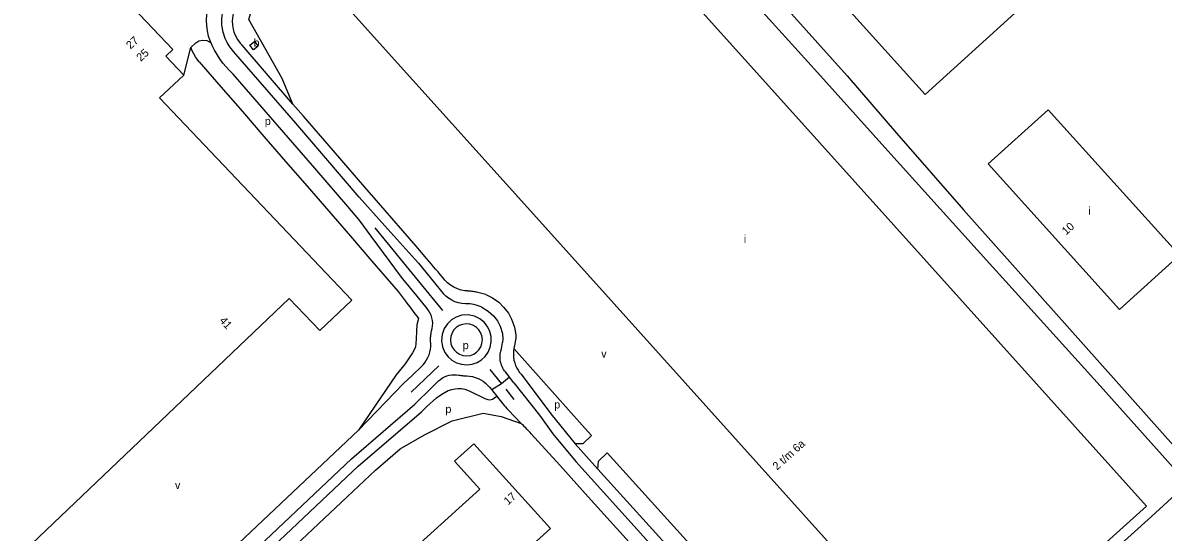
# Model space of a CAD drawing. Extents: x 156097 to 158136, y 385644 to 388348.
# Drawn here: x 156386 to 156956, y 387555 to 387809 of the extents above; entities that cross this region are included whole.
import ezdxf

# ---------------------------------------------------------------- set-up
doc = ezdxf.new("R2010")
doc.units = 0
for name, color, linetype in [('BLT_Basislijn', 7, 'Continuous'), ('BLT_Bebouwing', 7, 'Continuous'), ('BLT_Centroide', 7, 'Continuous'), ('BLT_Huisnummer', 7, 'Continuous'), ('BLT_Huisnummer_reeks', 7, 'Continuous'), ('BLT_Vlakafsluiter', 7, 'Continuous')]:
    doc.layers.add(name, color=color, linetype=linetype)

msp = doc.modelspace()

# ---------------------------------------------------------------- linework, layer by layer
at = {"layer": 'BLT_Basislijn'}
for p, q in [((156797.75, 387782.82), (156644.38, 387953.86)), ((156782.89, 387784.42), (156650.83, 387931.69)), ((156466.18, 387783.18), (156469.74, 387796.91)), ((156782.89, 387784.42), (156818.11, 387745.39)), ((156838.17, 387723.2), (156818.11, 387745.39)), ((156561.75, 387706.8), (156583.3, 387680.38)), ((156583.45, 387689.27), (156595.92, 387674.06)), ((156869.02, 387689.03), (156874, 387683.54)), ((156583.3, 387680.38), (156595.45, 387665.58)), ((156615.21, 387667.23), (156614.27, 387667.61)), ((156583.52, 387661.55), (156582.76, 387658.42)), ((156582.57, 387655.34), (156582.33, 387651.33)), ((156582.76, 387658.42), (156582.57, 387655.34)), ((156589.89, 387654.57), (156590.07, 387655.37)), ((156582.33, 387651.33), (156582.09, 387647.33)), ((156589.62, 387648.96), (156589.52, 387650.42)), ((156580.51, 387644.53), (156576.87, 387638.94)), ((156582.09, 387647.33), (156580.51, 387644.53)), ((156576.87, 387638.94), (156572.33, 387633.42)), ((156593.68, 387637.95), (156579.9, 387624.84)), ((156572.33, 387633.42), (156553.53, 387605.91)), ((156619.24, 387636.12), (156624.93, 387628.99)), ((156631.22, 387629.55), (156629.05, 387632.32)), ((156553.53, 387605.91), (156576.01, 387629.14)), ((156627.09, 387626.3), (156631.09, 387621.18)), ((156631.22, 387629.55), (156643.96, 387613.36)), ((156643.96, 387613.36), (156650.67, 387604.05)), ((156650.67, 387604.05), (156662.1, 387590.2)), ((156665.62, 387598.94), (156661.89, 387598.94)), ((156661.89, 387598.94), (156673.23, 387586.41)), ((156665.62, 387598.94), (156670.05, 387603.2)), ((156787.54, 387473.33), (156677.9, 387594.53)), ((156453.11, 387500.09), (156549.98, 387591.56)), ((156456.58, 387496.48), (156553.32, 387587.84)), ((156673.23, 387586.41), (156780.91, 387467.5))]:
    msp.add_line(p, q, dxfattribs=at)
for points in [[(156583.45, 387689.27), (156578.73, 387694.48), (156566.66, 387707.87), (156553.82, 387722.16), (156537.27, 387741.73), (156522.14, 387759.18), (156491.06, 387794.97), (156489.86, 387796.38), (156488.92, 387797.7), (156487.91, 387799.38), (156486.9, 387801.42), (156485.84, 387804.66), (156485.26, 387808.12), (156485.21, 387811.17), (156485.77, 387815.29), (156486.44, 387817.6), (156487.19, 387819.37), (156488.39, 387821.56), (156489.76, 387823.53), (156492.22, 387826.16), (156602.46, 387928.57), (156606.37, 387932.32), (156616.1, 387941.58), (156622.93, 387948.05)], [(156629.52, 387949.24), (156618.62, 387938.99), (156570.53, 387893.25), (156498.62, 387825.16), (156496.11, 387823.09), (156494.55, 387821.31), (156493.23, 387819.46), (156492.38, 387817.85), (156491.57, 387815.96), (156490.9, 387813.77), (156490.56, 387811.73), (156490.41, 387809.85), (156490.47, 387808.46), (156490.75, 387806.78), (156491.23, 387804.79), (156491.95, 387803.03), (156493.06, 387800.95), (156494.35, 387799.07), (156495.29, 387798.03)], [(156520.76, 387768.68), (156515.32, 387781.45), (156498.76, 387810.93), (156500.45, 387816.59), (156620.2, 387930.86), (156627.77, 387938.06), (156650.83, 387931.69)], [(156478.58, 387802.58), (156477.98, 387805.26), (156477.64, 387807.83), (156477.57, 387810.54), (156477.71, 387813.25), (156478.08, 387816.16)], [(156469.74, 387796.91), (156472.22, 387799.22), (156473.78, 387800.26), (156475.52, 387800.59), (156477.63, 387800.48), (156479.8, 387799.34)], [(156479.8, 387799.34), (156479.43, 387800.21), (156478.58, 387802.58)], [(156490.91, 387783.63), (156489.09, 387785.37), (156487.36, 387787.22), (156485.73, 387789.18), (156484.22, 387791.24), (156482.82, 387793.38), (156481.56, 387795.6), (156480.43, 387797.88), (156479.8, 387799.34)], [(156520.76, 387768.68), (156495.29, 387798.03)], [(156473.26, 387790.65), (156472.02, 387792.32), (156470.42, 387795.19), (156469.74, 387796.91)], [(156473.9, 387789.78), (156473.26, 387790.65)], [(156473.9, 387789.78), (156484.69, 387777.34), (156495.48, 387764.91), (156506.28, 387752.47), (156517.07, 387740.04), (156527.86, 387727.61), (156538.65, 387715.17), (156549.45, 387702.74), (156560.24, 387690.31), (156573.4, 387675.14)], [(156574.52, 387682.96), (156559.8, 387702.79), (156554.31, 387710.2), (156553.69, 387710.97), (156548.27, 387717.51), (156531.73, 387736.66), (156516.25, 387754.49), (156490.91, 387783.63)], [(156797.75, 387782.82), (156822.39, 387754.16)], [(156587.71, 387691.35), (156582.39, 387697.7), (156563.47, 387719.41), (156556.63, 387727.22), (156540.95, 387745.35), (156525.98, 387762.66), (156520.76, 387768.68)], [(156822.39, 387754.16), (156856.01, 387715.91), (156962.28, 387596.74)], [(156869.02, 387689.03), (156838.17, 387723.2)], [(156595.53, 387682.2), (156594.41, 387683.51), (156593.29, 387684.82), (156592.18, 387686.12), (156591.06, 387687.43), (156589.95, 387688.74), (156588.83, 387690.04), (156587.71, 387691.35)], [(156874, 387683.54), (156924.28, 387627.93)], [(156587.8, 387666.65), (156582.86, 387672.68), (156575.74, 387681.37), (156574.52, 387682.96)], [(156606.62, 387675.42), (156604.78, 387675.79), (156602.97, 387676.38), (156601.22, 387677.18), (156599.56, 387678.19), (156598.05, 387679.38), (156596.69, 387680.73), (156595.53, 387682.2)], [(156573.4, 387675.14), (156577.36, 387669.83), (156578.24, 387668.65), (156579.12, 387667.46), (156580, 387666.28), (156580.88, 387665.1), (156581.76, 387663.92), (156582.64, 387662.73), (156583.52, 387661.55)], [(156607, 387668.94), (156605.24, 387669.07), (156603.48, 387669.41), (156601.75, 387669.97), (156600.1, 387670.73), (156598.56, 387671.69), (156597.16, 387672.81), (156595.92, 387674.06)], [(156608.5, 387675.29), (156608.23, 387675.31), (156607.96, 387675.33), (156607.7, 387675.35), (156607.43, 387675.36), (156607.16, 387675.38), (156606.89, 387675.4), (156606.62, 387675.42)], [(156612.53, 387674.78), (156611.96, 387674.89), (156611.39, 387674.99), (156610.81, 387675.08), (156610.24, 387675.15), (156609.66, 387675.21), (156609.08, 387675.26), (156608.5, 387675.29)], [(156617.12, 387673.59), (156616.46, 387673.76), (156615.81, 387673.93), (156615.15, 387674.1), (156614.5, 387674.27), (156613.84, 387674.44), (156613.19, 387674.61), (156612.53, 387674.78)], [(156617.12, 387673.59), (156620.47, 387671.91), (156623.61, 387669.76), (156626.21, 387667.16), (156628.44, 387664.29), (156629.99, 387661.25), (156631.45, 387657.26), (156632.12, 387653.44), (156632.2, 387651.75), (156631.57, 387648.1)], [(156590.07, 387655.37), (156590.38, 387656.63), (156590.57, 387657.94), (156590.6, 387659.28), (156590.49, 387660.63), (156590.22, 387661.96), (156589.8, 387663.26), (156589.25, 387664.48), (156588.58, 387665.62), (156587.8, 387666.65)], [(156614.27, 387667.61), (156613.28, 387667.97), (156612.26, 387668.27), (156611.22, 387668.52), (156610.17, 387668.71), (156609.12, 387668.84), (156608.06, 387668.92), (156607, 387668.94)], [(156615.21, 387667.23), (156618.4, 387665.19), (156621, 387662.86), (156622.96, 387660.42), (156624.31, 387657.72), (156625.43, 387654.14), (156625.66, 387651.32), (156625.53, 387649.54)], [(156618.21, 387657.35), (156616.54, 387659.55), (156614.24, 387661.44), (156611.43, 387662.78), (156608.33, 387663.38), (156605.22, 387663.2), (156602.38, 387662.31), (156600, 387660.91), (156597.98, 387659.01), (156596.34, 387656.53), (156595.3, 387653.6), (156595.02, 387650.45), (156595.52, 387647.38), (156596.7, 387644.65), (156598.34, 387642.42)], [(156589.52, 387650.42), (156589.51, 387650.88), (156589.51, 387651.35), (156589.53, 387651.81), (156589.56, 387652.28), (156589.6, 387652.74), (156589.65, 387653.2), (156589.72, 387653.66), (156589.8, 387654.12), (156589.89, 387654.57)], [(156598.34, 387642.42), (156600.19, 387640.8), (156602.46, 387639.51), (156605.03, 387638.71), (156607.74, 387638.47), (156610.41, 387638.82), (156612.86, 387639.69), (156614.97, 387640.97), (156616.78, 387642.64), (156618.31, 387644.75), (156619.39, 387647.22), (156619.92, 387649.89), (156619.86, 387652.58), (156619.25, 387655.11), (156618.21, 387657.35)], [(156602.4, 387657.12), (156601.22, 387655.93), (156600.27, 387654.42), (156599.66, 387652.67), (156599.47, 387650.79), (156599.72, 387648.95), (156600.35, 387647.29), (156601.27, 387645.89), (156602.46, 387644.71), (156603.96, 387643.75), (156605.71, 387643.14), (156607.59, 387642.94), (156609.43, 387643.19), (156611.1, 387643.82), (156612.5, 387644.73)], [(156612.5, 387644.73), (156613.68, 387645.92), (156614.63, 387647.43), (156615.24, 387649.18), (156615.43, 387651.05), (156615.19, 387652.9), (156614.55, 387654.57), (156613.64, 387655.97), (156612.45, 387657.15), (156610.94, 387658.1), (156609.19, 387658.72), (156607.31, 387658.91), (156605.47, 387658.66), (156603.8, 387658.03), (156602.4, 387657.12)], [(156585.02, 387637.64), (156585.97, 387638.63), (156586.83, 387639.72), (156587.59, 387640.9), (156588.25, 387642.16), (156588.78, 387643.47), (156589.19, 387644.83), (156589.46, 387646.21), (156589.6, 387647.59), (156589.62, 387648.96)], [(156625.36, 387648.68), (156625.53, 387649.54)], [(156626.95, 387634.94), (156626.49, 387635.54), (156626.06, 387636.19), (156625.67, 387636.87), (156625.32, 387637.58), (156625.02, 387638.31), (156624.76, 387639.07), (156624.56, 387639.85), (156624.42, 387640.64), (156624.32, 387641.43), (156624.28, 387642.22), (156624.3, 387643.01), (156624.36, 387643.79), (156624.48, 387644.56), (156624.64, 387645.31)], [(156624.64, 387645.31), (156624.93, 387646.42), (156625.17, 387647.55), (156625.36, 387648.68)], [(156631.22, 387646.66), (156631.01, 387645.19), (156630.94, 387643.71), (156631.02, 387642.24), (156631.24, 387640.8), (156631.6, 387639.42), (156632.07, 387638.11), (156632.65, 387636.87), (156633.32, 387635.73), (156634.06, 387634.68), (156634.85, 387633.74)], [(156631.57, 387648.1), (156631.22, 387646.66)], [(156670.05, 387603.2), (156665.35, 387608.41), (156631.22, 387646.66)], [(156576.01, 387629.14), (156580.48, 387633.36), (156585.02, 387637.64)], [(156593.51, 387630.45), (156594.43, 387631.21), (156595.44, 387631.89), (156596.53, 387632.46), (156597.69, 387632.92), (156598.89, 387633.26), (156600.12, 387633.46), (156601.35, 387633.54), (156602.57, 387633.48), (156603.75, 387633.31)], [(156603.75, 387633.31), (156604.18, 387633.23), (156604.62, 387633.17), (156605.05, 387633.11), (156605.49, 387633.05), (156605.93, 387633.01), (156606.36, 387632.97), (156606.8, 387632.95), (156607.24, 387632.93), (156607.68, 387632.91)], [(156607.68, 387632.91), (156609.09, 387632.81), (156610.51, 387632.57), (156611.92, 387632.19), (156613.29, 387631.67), (156614.6, 387631.01), (156615.85, 387630.23), (156617, 387629.34), (156618.05, 387628.36), (156618.98, 387627.3)], [(156629.05, 387632.32), (156628.67, 387632.79), (156626.95, 387634.94)], [(156634.85, 387633.74), (156649.59, 387613.99), (156661.89, 387598.94)], [(156553.32, 387587.84), (156585.02, 387615.04), (156587.73, 387617.66), (156592.43, 387621.9), (156595.23, 387623.89), (156598.31, 387625.6), (156600.12, 387626.21), (156601.82, 387626.53), (156603.35, 387626.6), (156605.08, 387626.57), (156606.64, 387626.24), (156608.76, 387625.43), (156616.75, 387621.64), (156618.09, 387621.09), (156619.16, 387621.06), (156620.47, 387621.32), (156622.68, 387622.73)], [(156584.26, 387621.26), (156587.65, 387624.63), (156593.51, 387630.45)], [(156618.98, 387627.3), (156620.09, 387625.96)], [(156924.28, 387627.93), (156967.86, 387579.23)], [(156549.98, 387591.56), (156581.65, 387618.74), (156584.26, 387621.26)], [(156620.09, 387625.96), (156620.47, 387625.5), (156622.68, 387622.73)], [(156622.68, 387622.73), (156623.04, 387622.29), (156626.35, 387618.2), (156626.99, 387617.42), (156627.6, 387616.65), (156628.28, 387615.93), (156634.84, 387609.22)], [(156561.98, 387585.89), (156574.33, 387596.58), (156586.47, 387603.58), (156600.32, 387610.43), (156615.88, 387614.29), (156624.87, 387612.72), (156634.84, 387609.22)], [(156639.85, 387604.07), (156639.31, 387604.66), (156638.77, 387605.24), (156638.22, 387605.83), (156637.67, 387606.4), (156637.11, 387606.98), (156636.55, 387607.54), (156635.98, 387608.11), (156635.41, 387608.67), (156634.84, 387609.22)], [(156457.96, 387515.67), (156553.53, 387605.91)], [(156639.85, 387604.07), (156654.08, 387588.33), (156668.32, 387572.59), (156682.55, 387556.85), (156696.79, 387541.11), (156711.03, 387525.38), (156725.26, 387509.64), (156731.92, 387502.28)], [(156673.23, 387586.41), (156673.43, 387590.32), (156677.9, 387594.53)], [(156662.1, 387590.2), (156683.63, 387566.4), (156705.16, 387542.59), (156726.69, 387518.79), (156748.23, 387494.98), (156769.76, 387471.18), (156791.29, 387447.37), (156812.83, 387423.56), (156834.36, 387399.76)], [(156561.98, 387585.89), (156547.79, 387572.51), (156533.59, 387559.12), (156519.4, 387545.73), (156505.2, 387532.35), (156491, 387518.96), (156476.81, 387505.57), (156463.51, 387493.03)], [(156853.51, 387475.85), (156949.84, 387562.64), (156967.86, 387579.23)]]:
    msp.add_lwpolyline(points, dxfattribs=at)
at = {"layer": 'BLT_Bebouwing'}
for points in [[(156675.66, 387951.87), (156720.5, 387992.39), (156881.67, 387814.03), (156836.85, 387773.51)], [(156499.17, 387798.02), (156501.53, 387799.97), (156503.44, 387797.67), (156501.07, 387795.72)], [(156868.27, 387738.76), (156898.25, 387765.85), (156963.88, 387693.2), (156933.91, 387666.14)], [(156611.15, 387599.01), (156601.5, 387590.29), (156614.14, 387576.3), (156512.4, 387484.25), (156497.8, 387500.29), (156493.5, 387496.38), (156508.11, 387480.23), (156503.37, 387475.95), (156516.05, 387461.92), (156510.4, 387456.79), (156514.78, 387451.94), (156520.47, 387457.09), (156528.96, 387447.68), (156533.66, 387451.93), (156566.4, 387415.83), (156570.67, 387419.71), (156538.05, 387455.9), (156649.49, 387556.67)]]:
    msp.add_lwpolyline(points, close=True, dxfattribs=at)
for points in [[(156766.18, 387769.32), (156633.84, 387916.21), (156537.02, 387829.14), (156669.51, 387682.08)], [(156246.82, 387772.59), (156370.75, 387890.36), (156460.64, 387795.89)], [(156460.64, 387795.89), (156457.2, 387792.62), (156466.18, 387783.18)], [(156466.18, 387783.18), (156454.13, 387771.74)], [(156454.13, 387771.74), (156550.24, 387670.79), (156534.16, 387655.61), (156518.91, 387671.61), (156333.02, 387494.74)], [(156669.51, 387682.08), (156835.12, 387497.93), (156819.12, 387483.53), (156834.49, 387466.37), (156947.36, 387567.96), (156766.18, 387769.32)]]:
    msp.add_lwpolyline(points, dxfattribs=at)
at = {"layer": 'BLT_Vlakafsluiter'}
for p, q in [((156629.05, 387632.32), (156624.93, 387628.99)), ((156624.93, 387628.99), (156620.09, 387625.96))]:
    msp.add_line(p, q, dxfattribs=at)

# ---------------------------------------------------------------- texts
at = {"layer": 'BLT_Centroide'}
for s, p in [('b', (156501.06, 387797.34)), ('p', (156506.68, 387758.21)), ('i', (156918.4, 387713.37)), ('i', (156746.13, 387699.38)), ('p', (156605.63, 387646.27)), ('v', (156674.86, 387642.03)), ('p', (156596.97, 387614.38)), ('p', (156651.39, 387616.68)), ('v', (156461.79, 387576.4))]:
    msp.add_text(s, height=4, dxfattribs=at).set_placement(p)
at = {"layer": 'BLT_Huisnummer'}
for s, rotation, p in [('10', 42.337, (156907.28, 387703.05)), ('17', 41.7508, (156628.29, 387568.2))]:
    msp.add_text(s, height=4, rotation=rotation, dxfattribs=at).set_placement(p)
at = {"layer": 'BLT_Huisnummer_reeks'}
for s, rotation, p in [('27', 41.7508, (156439.54, 387795.88)), ('25', 41.7508, (156444.67, 387789.74)), ('41', 311.7508, (156483.74, 387660.34)), ('2 t/m 6a', 41.7508, (156762.71, 387585.63))]:
    msp.add_text(s, height=4, rotation=rotation, dxfattribs=at).set_placement(p)

doc.saveas('drawing.dxf')
